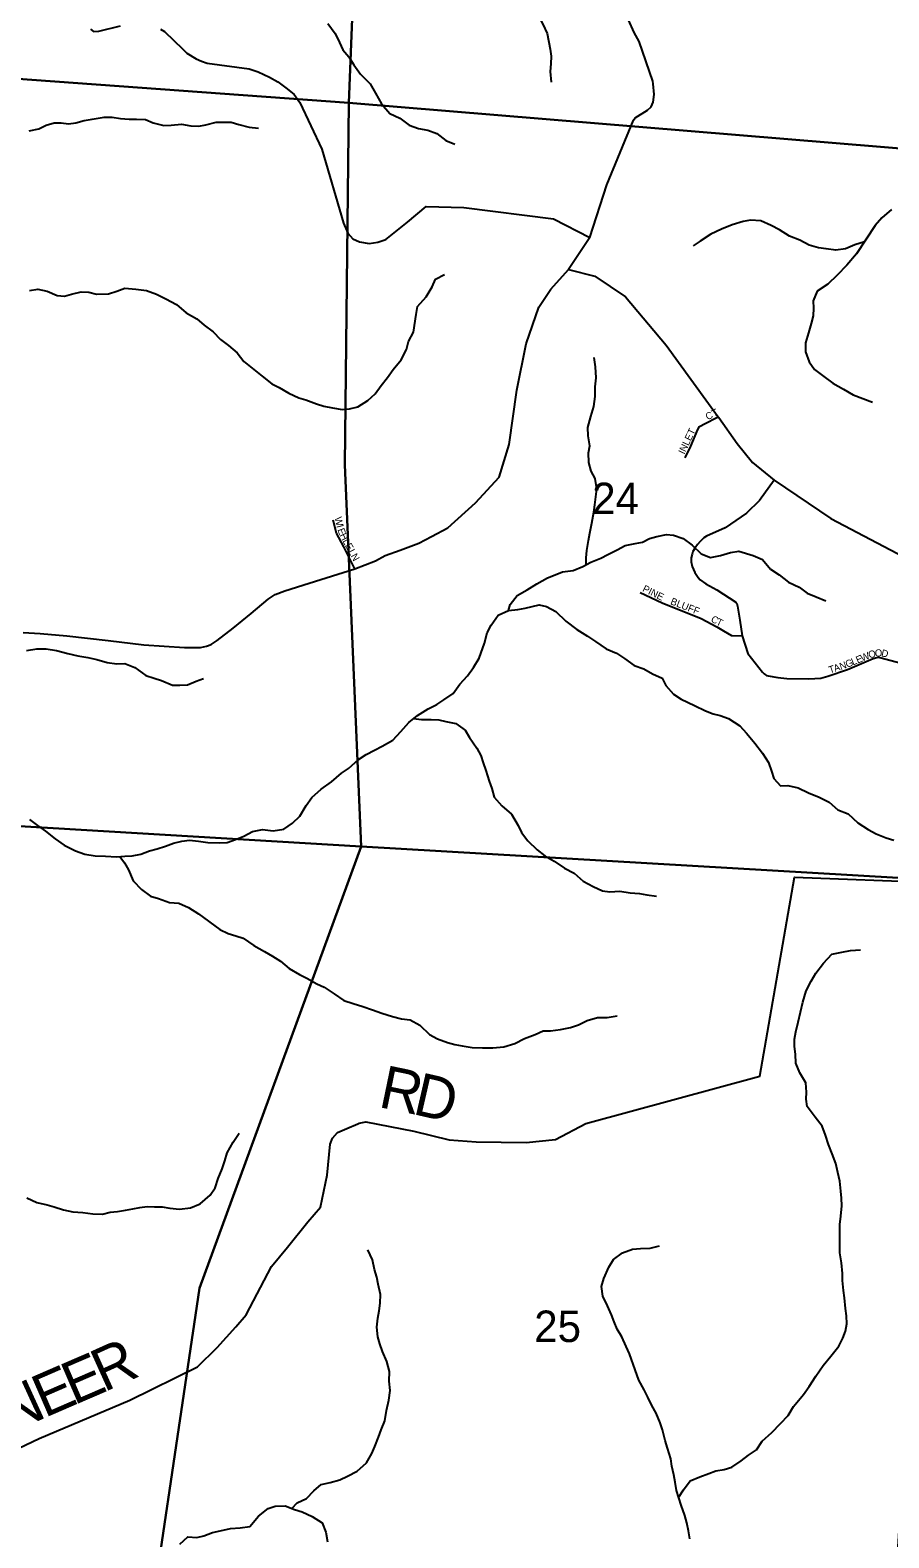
# Model space of a CAD drawing. Extents: x 1624196 to 2029251, y 146837 to 440034.
# Drawn here: x 1876586 to 1882613, y 286109 to 296690 of the extents above; entities that cross this region are included whole.
import ezdxf

# ---------------------------------------------------------------- set-up
doc = ezdxf.new("R2010")
doc.units = 0
for name, color, linetype in [('GM_X_County_Road', 7, 'Continuous'), ('GM_X_County_Road_Text', 7, 'Continuous'), ('GM_X_Minor_River', 7, 'Continuous'), ('GM_X_Section', 7, 'Continuous'), ('GM_X_Section_Text', 7, 'Continuous'), ('GM_X_Township_Road', 7, 'Continuous'), ('GM_X_Township_Subdivision', 7, 'Continuous'), ('GM_X_Township_Subdivision_Text', 7, 'Continuous')]:
    doc.layers.add(name, color=color, linetype=linetype)

msp = doc.modelspace()

# ---------------------------------------------------------------- linework, layer by layer
at = {"layer": 'GM_X_County_Road'}
for points in [[(1876538, 292462), (1876656, 292455), (1876843, 292439), (1877133, 292406), (1877384, 292377), (1877670, 292358), (1877742, 292358), (1877782, 292357), (1877824, 292366), (1877857, 292379), (1877899, 292406), (1878011, 292492), (1878138, 292596), (1878257, 292697), (1878307, 292730), (1878374, 292756), (1878545, 292809), (1878866, 292909), (1879011, 292966), (1879079, 293003), (1879183, 293041), (1879314, 293089), (1879404, 293136), (1879517, 293198), (1879713, 293373), (1879878, 293553), (1879948, 293782), (1880003, 294162), (1880068, 294488), (1880157, 294746), (1880241, 294871), (1880365, 295009), (1880549, 294963), (1880764, 294818), (1881051, 294480), (1881415, 293977), (1881419, 293972), (1881549, 293789), (1881657, 293655), (1881809, 293531), (1882206, 293263), (1882857, 292921)], [(1874845, 285949), (1876649, 286806), (1877285, 287076), (1877762, 287309), (1877900, 287444), (1878030, 287590), (1878103, 287674), (1878280, 288014), (1878393, 288150), (1878535, 288326), (1878623, 288429), (1878670, 288655), (1878693, 288872), (1878708, 288913), (1878744, 288954), (1878810, 288982), (1878887, 289015), (1878895, 289019), (1878942, 289029), (1879280, 288962), (1879528, 288901), (1879716, 288888), (1880067, 288884), (1880274, 288905), (1880486, 289017), (1881707, 289348), (1881952, 290745), (1882941, 290709)]]:
    msp.add_lwpolyline(points, dxfattribs=at)
at = {"layer": 'GM_X_Minor_River'}
for points in [[(1879452, 297770), (1879508, 297764), (1879578, 297715), (1879608, 297663), (1879634, 297613), (1879681, 297544), (1879751, 297480), (1879807, 297403), (1879847, 297335), (1879887, 297259), (1879922, 297186), (1879966, 297120), (1880002, 297056), (1880038, 297005), (1880055, 296945), (1880081, 296875), (1880139, 296810), (1880185, 296732), (1880216, 296666), (1880236, 296557), (1880242, 296507), (1880241, 296453), (1880235, 296399), (1880243, 296325)], [(1878676, 296737), (1878726, 296666), (1878758, 296604), (1878782, 296552), (1878822, 296502), (1878859, 296447), (1878905, 296381), (1878973, 296314), (1879011, 296248), (1879052, 296172), (1879110, 296105), (1879180, 296071), (1879246, 296022), (1879312, 296000), (1879378, 295988), (1879440, 295965), (1879504, 295915), (1879568, 295889)], [(1876580, 295983), (1876648, 295998), (1876698, 296022), (1876754, 296040), (1876804, 296040), (1876856, 296033), (1876907, 296039), (1876965, 296055), (1877021, 296065), (1877105, 296078), (1877161, 296080), (1877221, 296070), (1877281, 296066), (1877333, 296065), (1877397, 296063), (1877449, 296039), (1877525, 296020), (1877577, 296022), (1877648, 296030), (1877714, 296019), (1877770, 296015), (1877820, 296025), (1877892, 296043), (1877948, 296044), (1877998, 296044), (1878050, 296028), (1878124, 296008), (1878188, 296001)], [(1882631, 295430), (1882564, 295372), (1882518, 295318), (1882385, 295120), (1882318, 295040), (1882250, 294970), (1882184, 294906), (1882111, 294857), (1882083, 294789), (1882085, 294738), (1882082, 294684), (1882068, 294632), (1882050, 294566), (1882029, 294496), (1882029, 294432), (1882053, 294362), (1882091, 294309), (1882157, 294259), (1882220, 294212), (1882294, 294170), (1882362, 294130), (1882430, 294105), (1882498, 294079)], [(1882442, 295205), (1882375, 295182), (1882309, 295154), (1882241, 295145), (1882173, 295155), (1882119, 295163), (1882055, 295180), (1881989, 295216), (1881915, 295244), (1881845, 295289), (1881787, 295319), (1881715, 295352), (1881643, 295356), (1881591, 295346), (1881514, 295324), (1881438, 295293), (1881364, 295257), (1881289, 295209), (1881239, 295175)], [(1876581, 294862), (1876641, 294872), (1876705, 294859), (1876777, 294827), (1876827, 294823), (1876877, 294836), (1876945, 294854), (1876999, 294850), (1877053, 294836), (1877136, 294839), (1877194, 294857), (1877250, 294879), (1877328, 294872), (1877402, 294862), (1877474, 294836), (1877538, 294803), (1877614, 294765), (1877682, 294706), (1877756, 294664), (1877808, 294620), (1877871, 294573), (1877923, 294519), (1877979, 294476), (1878039, 294426), (1878085, 294364), (1878145, 294317), (1878215, 294261), (1878282, 294208), (1878334, 294182), (1878402, 294142), (1878472, 294109), (1878522, 294095), (1878596, 294067), (1878648, 294050), (1878708, 294038), (1878776, 294028), (1878828, 294031), (1878885, 294047), (1878957, 294091), (1879007, 294137), (1879050, 294197), (1879094, 294253), (1879134, 294307), (1879191, 294375), (1879227, 294449), (1879241, 294505), (1879276, 294571), (1879296, 294695), (1879306, 294751), (1879365, 294819), (1879407, 294889), (1879431, 294941), (1879494, 294975)], [(1880488, 292938), (1880488, 292987), (1880493, 293039), (1880505, 293108), (1880515, 293160), (1880528, 293230), (1880542, 293308), (1880550, 293358), (1880563, 293470), (1880553, 293544), (1880525, 293595), (1880507, 293655), (1880506, 293723), (1880514, 293773), (1880502, 293843), (1880500, 293902), (1880521, 293978), (1880543, 294048), (1880552, 294118), (1880552, 294186), (1880558, 294250), (1880554, 294328), (1880545, 294393)], [(1879944, 292617), (1879956, 292659), (1880004, 292723), (1880075, 292761), (1880143, 292804), (1880217, 292846), (1880270, 292868), (1880322, 292888), (1880398, 292897), (1880466, 292925), (1880522, 292957), (1880591, 292985), (1880641, 293009), (1880707, 293042), (1880763, 293074), (1880833, 293088), (1880883, 293096), (1880934, 293122), (1880984, 293137), (1881052, 293151), (1881102, 293145), (1881170, 293121), (1881232, 293076), (1881296, 293014), (1881362, 292989), (1881432, 293003), (1881502, 293023), (1881560, 293033), (1881660, 293004), (1881726, 292974), (1881782, 292907), (1881844, 292867), (1881910, 292816), (1881984, 292780), (1882040, 292738), (1882104, 292713), (1882170, 292685)], [(1879380, 291926), (1879440, 291957), (1879490, 291989), (1879555, 292035), (1879601, 292099), (1879655, 292159), (1879698, 292217), (1879738, 292283), (1879775, 292387), (1879795, 292459), (1879821, 292515), (1879870, 292583), (1879944, 292617), (1880008, 292625), (1880060, 292634), (1880110, 292646), (1880160, 292656), (1880210, 292646), (1880276, 292609), (1880346, 292541), (1880424, 292484), (1880498, 292436), (1880554, 292400), (1880630, 292349), (1880702, 292317), (1880758, 292280), (1880826, 292230), (1880894, 292208), (1880955, 292173), (1881021, 292141), (1881049, 292091), (1881101, 292030), (1881155, 291994), (1881249, 291951), (1881327, 291913), (1881379, 291891), (1881429, 291880), (1881487, 291860), (1881567, 291807), (1881615, 291757), (1881672, 291687), (1881726, 291616), (1881768, 291550), (1881790, 291490), (1881807, 291437), (1881853, 291387), (1881903, 291389), (1881977, 291373), (1882049, 291338), (1882123, 291306), (1882195, 291271), (1882255, 291219), (1882327, 291190), (1882395, 291126), (1882469, 291080), (1882525, 291049), (1882595, 291021), (1882649, 291005)], [(1876561, 292336), (1876634, 292347), (1876698, 292349), (1876772, 292335), (1876850, 292314), (1876922, 292298), (1876992, 292287), (1877054, 292273), (1877126, 292253), (1877194, 292242), (1877250, 292244), (1877320, 292216), (1877398, 292161), (1877456, 292141), (1877508, 292125), (1877586, 292092), (1877638, 292092), (1877690, 292096), (1877752, 292120), (1877802, 292139)], [(1876582, 291150), (1876638, 291108), (1876694, 291068), (1876762, 291015), (1876826, 290969), (1876904, 290930), (1876970, 290908), (1877042, 290896), (1877114, 290893), (1877192, 290889), (1877250, 290893), (1877302, 290895), (1877364, 290906), (1877423, 290930), (1877477, 290944), (1877537, 290964), (1877593, 290985), (1877651, 290999), (1877705, 291005), (1877767, 290999), (1877833, 290988), (1877914, 290986), (1877968, 290988), (1878028, 291010), (1878086, 291033), (1878148, 291065), (1878216, 291079), (1878292, 291070), (1878367, 291082), (1878427, 291124), (1878479, 291174), (1878524, 291248), (1878564, 291304), (1878628, 291364), (1878701, 291415), (1878771, 291475), (1878821, 291509), (1878890, 291571), (1878944, 291607), (1879004, 291637), (1879058, 291664), (1879131, 291706), (1879189, 291768), (1879243, 291832), (1879304, 291880), (1879380, 291926)], [(1879277, 291858), (1879334, 291852), (1879400, 291853), (1879454, 291849), (1879504, 291837), (1879574, 291823), (1879640, 291778), (1879671, 291726), (1879721, 291651), (1879749, 291599), (1879765, 291547), (1879785, 291493), (1879808, 291420), (1879826, 291368), (1879842, 291308), (1879898, 291246), (1879964, 291187), (1880011, 291109), (1880035, 291059), (1880079, 291000), (1880145, 290938), (1880199, 290895), (1880265, 290857), (1880336, 290809), (1880404, 290774), (1880468, 290718), (1880538, 290679), (1880604, 290649), (1880654, 290643), (1880724, 290648), (1880798, 290636), (1880864, 290632), (1880914, 290621), (1880983, 290611)], [(1877216, 290891), (1877248, 290847), (1877276, 290796), (1877309, 290720), (1877367, 290658), (1877431, 290613), (1877487, 290595), (1877565, 290568), (1877631, 290564), (1877697, 290532), (1877769, 290487), (1877917, 290378), (1877975, 290350), (1878031, 290334), (1878081, 290318), (1878157, 290265), (1878231, 290223), (1878287, 290192), (1878344, 290156), (1878404, 290104), (1878476, 290063), (1878528, 290037), (1878598, 289996), (1878650, 289974), (1878720, 289926), (1878788, 289881), (1878854, 289859), (1878922, 289839), (1878990, 289814), (1879054, 289792), (1879130, 289767), (1879192, 289751), (1879254, 289745), (1879322, 289706), (1879388, 289642), (1879446, 289610), (1879516, 289585), (1879568, 289571), (1879618, 289561), (1879688, 289550), (1879762, 289548), (1879834, 289548), (1879910, 289555), (1879988, 289579), (1880057, 289613), (1880131, 289641), (1880187, 289666), (1880239, 289668), (1880309, 289676), (1880378, 289690), (1880436, 289709), (1880496, 289739), (1880568, 289761), (1880636, 289761), (1880706, 289772)], [(1881137, 286393), (1881172, 286446), (1881219, 286510), (1881287, 286536), (1881349, 286561), (1881399, 286579), (1881457, 286589), (1881510, 286605), (1881576, 286649), (1881628, 286690), (1881684, 286726), (1881725, 286788), (1881793, 286848), (1881853, 286912), (1881906, 286968), (1881944, 287030), (1882015, 287116), (1882053, 287172), (1882101, 287244), (1882152, 287318), (1882206, 287384), (1882262, 287454), (1882291, 287510), (1882309, 287560), (1882319, 287612), (1882315, 287668), (1882310, 287718), (1882302, 287794), (1882294, 287844), (1882287, 287915), (1882289, 287965), (1882281, 288039), (1882269, 288109), (1882268, 288161), (1882268, 288235), (1882270, 288308), (1882275, 288366), (1882283, 288438), (1882281, 288492), (1882277, 288542), (1882268, 288612), (1882256, 288673), (1882242, 288735), (1882216, 288803), (1882189, 288869), (1882169, 288936), (1882145, 288998), (1882095, 289062), (1882040, 289137), (1882032, 289187), (1882036, 289237), (1882030, 289303), (1881989, 289372), (1881961, 289440), (1881957, 289504), (1881951, 289558), (1881952, 289608), (1881960, 289660), (1881976, 289728), (1881992, 289799), (1882009, 289869), (1882033, 289947), (1882068, 290015), (1882100, 290071), (1882154, 290143), (1882213, 290205), (1882283, 290218), (1882345, 290232), (1882415, 290236)], [(1877935, 288698), (1877952, 288754), (1877970, 288810), (1878012, 288886), (1878053, 288950)], [(1876562, 288494), (1876634, 288463), (1876706, 288445), (1876756, 288433), (1876820, 288410), (1876886, 288398), (1876957, 288392), (1877027, 288383), (1877093, 288381), (1877149, 288395), (1877199, 288399), (1877255, 288408), (1877307, 288418), (1877357, 288428), (1877407, 288434), (1877459, 288432), (1877514, 288431), (1877566, 288423), (1877634, 288415), (1877712, 288426), (1877780, 288454), (1877850, 288514), (1877885, 288566), (1877907, 288630), (1877935, 288698)], [(1878423, 286315), (1878460, 286354), (1878526, 286386), (1878578, 286438), (1878629, 286483), (1878691, 286497), (1878759, 286515), (1878813, 286541), (1878881, 286577), (1878946, 286636), (1878984, 286700), (1879006, 286750), (1879031, 286816), (1879049, 286868), (1879075, 286931), (1879088, 287003), (1879104, 287075), (1879112, 287143), (1879105, 287209), (1879109, 287277), (1879089, 287346), (1879059, 287416), (1879040, 287470), (1879026, 287520), (1879020, 287588), (1879026, 287651), (1879035, 287701), (1879043, 287755), (1879045, 287817), (1879029, 287889), (1879020, 287939), (1879002, 287992), (1878990, 288060), (1878956, 288130)], [(1881217, 286101), (1881207, 286159), (1881195, 286215), (1881182, 286265), (1881156, 286338), (1881138, 286390), (1881122, 286442), (1881114, 286500), (1881105, 286552), (1881091, 286613), (1881083, 286663), (1881059, 286739), (1881044, 286793), (1881024, 286866), (1881008, 286916), (1880980, 286984), (1880949, 287038), (1880921, 287097), (1880895, 287147), (1880859, 287215), (1880832, 287288), (1880792, 287400), (1880770, 287452), (1880740, 287519), (1880707, 287573), (1880685, 287625), (1880667, 287675), (1880639, 287738), (1880605, 287806), (1880596, 287874), (1880612, 287930), (1880648, 288008), (1880681, 288062), (1880743, 288110), (1880815, 288134), (1880869, 288140), (1880939, 288143), (1881004, 288159)], [(1877637, 286065), (1877692, 286117), (1877756, 286112), (1877806, 286122), (1877866, 286146), (1877942, 286162), (1877992, 286175), (1878060, 286179), (1878127, 286189), (1878189, 286261), (1878257, 286315), (1878307, 286332), (1878376, 286334), (1878442, 286308), (1878496, 286292), (1878565, 286259), (1878635, 286215), (1878661, 286148), (1878673, 286082)]]:
    msp.add_lwpolyline(points, dxfattribs=at)
at = {"layer": 'GM_X_Section'}
for points in [[(1874428, 302039), (1879932, 301784), (1878930, 298897), (1878822, 296179), (1874113, 296521)], [(1879932, 301784), (1883619, 301605), (1883310, 296580), (1883262, 295812), (1878822, 296179), (1878930, 298897)], [(1874113, 296521), (1878822, 296179), (1878796, 293639), (1878909, 290960), (1873797, 291264)], [(1878822, 296179), (1883262, 295812), (1883004, 291354), (1882960, 290724), (1878909, 290960), (1878796, 293639)], [(1873797, 291264), (1878909, 290960), (1877776, 287862), (1877329, 284849), (1874712, 284940), (1873310, 285573)], [(1878909, 290960), (1882960, 290724), (1882678, 286083), (1882574, 284429), (1877329, 284849), (1877776, 287862)]]:
    msp.add_lwpolyline(points, close=True, dxfattribs=at)
at = {"layer": 'GM_X_Township_Road'}
for points in [[(1880514, 295235), (1880634, 295604), (1880821, 296057), (1880833, 296074), (1880919, 296129), (1880946, 296152), (1880958, 296184), (1880965, 296239), (1880960, 296312), (1880957, 296332), (1880860, 296610), (1880826, 296674), (1880786, 296762), (1880764, 296825), (1880750, 296909), (1880743, 296971), (1880744, 297047), (1880752, 297122), (1880768, 297193), (1880867, 297445), (1881042, 297771), (1881049, 297804)], [(1877009, 296697), (1877031, 296680), (1877069, 296683), (1877220, 296720)], [(1877502, 296696), (1877529, 296680), (1877658, 296556), (1877687, 296529), (1877752, 296489), (1877788, 296471), (1877829, 296457), (1878123, 296417), (1878187, 296398), (1878267, 296360), (1878325, 296327), (1878390, 296277), (1878439, 296237), (1878479, 296182), (1878633, 295855), (1878785, 295335), (1878816, 295266), (1878850, 295224), (1878899, 295203), (1878966, 295193), (1879026, 295201), (1879082, 295221), (1879234, 295342), (1879366, 295452), (1879631, 295445), (1880260, 295366), (1880514, 295235), (1880365, 295009)]]:
    msp.add_lwpolyline(points, dxfattribs=at)
at = {"layer": 'GM_X_Township_Subdivision'}
for points in [[(1881184, 293689), (1881224, 293771), (1881272, 293887), (1881284, 293907), (1881293, 293913), (1881314, 293924), (1881415, 293977)], [(1881809, 293531), (1881706, 293388), (1881615, 293299), (1881465, 293198), (1881334, 293138), (1881314, 293126), (1881288, 293101), (1881269, 293081), (1881253, 293057), (1881238, 293031), (1881232, 293013), (1881225, 292987), (1881226, 292958), (1881233, 292926), (1881251, 292884), (1881275, 292848), (1881289, 292832), (1881328, 292804), (1881405, 292762), (1881540, 292676), (1881547, 292667), (1881551, 292648), (1881567, 292549), (1881584, 292440)], [(1878866, 292909), (1878787, 293063), (1878736, 293160), (1878713, 293250)], [(1880867, 292743), (1881023, 292670), (1881296, 292560), (1881407, 292502), (1881452, 292474), (1881508, 292441), (1881584, 292440)], [(1881584, 292440), (1881624, 292316), (1881726, 292184), (1881737, 292173), (1881748, 292166), (1881755, 292161), (1881766, 292158), (1881835, 292147), (1881898, 292140), (1882051, 292137), (1882135, 292141), (1882184, 292155), (1882322, 292204), (1882504, 292281), (1882528, 292288), (1882544, 292289), (1882551, 292287), (1882770, 292229), (1883035, 292181)]]:
    msp.add_lwpolyline(points, dxfattribs=at)

# ---------------------------------------------------------------- texts
at = {"layer": 'GM_X_County_Road_Text'}
for s, rotation, p in [('R', 348.3234, (1879023, 289134)), ('D', 347.0267, (1879263, 289085)), ('R', 24.285, (1877104, 287129)), ('E', 23.3263, (1876893, 287038)), ('E', 23.4721, (1876687, 286949)), ('N', 24.5657, (1876449, 286840))]:
    msp.add_text(s, height=300, rotation=rotation, dxfattribs=at).set_placement(p)
at = {"layer": 'GM_X_Section_Text'}
for s, p in [('24', (1880531, 293293)), ('25', (1880124, 287483))]:
    msp.add_text(s, height=221, rotation=0, dxfattribs=at).set_placement(p)
at = {"layer": 'GM_X_Township_Subdivision_Text'}
for s, rotation, p in [('CT', 26.576, (1881341, 293951)), ('INLET', 64.7241, (1881178, 293709)), ('W', 281.3049, (1878723, 293269)), ('I', 284.2301, (1878735, 293211)), ('E', 290.0805, (1878742, 293184)), ('H', 295.9309, (1878757, 293146)), ('L', 298.8562, (1878777, 293104)), ('E', 298.8562, (1878794, 293073)), ('L', 298.8562, (1878817, 293031)), ('N', 298.8562, (1878834, 293000)), ('PINE', 333.435, (1880879, 292754)), ('BLUFF', 338.8048, (1881076, 292662)), ('C', 330.2943, (1881359, 292542)), ('T', 333.5608, (1881396, 292521)), ('O', 2.8209, (1882516, 292293)), ('D', 348.1327, (1882557, 292296)), ('A', 18.4833, (1882234, 292185)), ('N', 18.9828, (1882276, 292199)), ('G', 21.866, (1882320, 292214)), ('L', 22.4681, (1882361, 292231)), ('E', 22.4559, (1882394, 292244)), ('W', 22.4414, (1882426, 292258)), ('O', 19.52, (1882479, 292279)), ('T', 18.4868, (1882200, 292174))]:
    msp.add_text(s, height=50, rotation=rotation, dxfattribs=at).set_placement(p)

doc.saveas('drawing.dxf')
